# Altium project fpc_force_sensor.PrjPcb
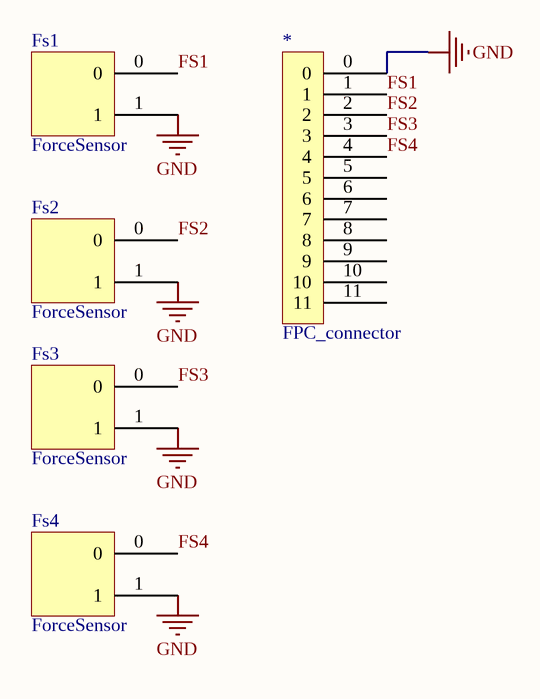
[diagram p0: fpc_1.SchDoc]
1 sheet, 5 parts. Net scope: global (net labels, ports and power ports of the same name join across sheets).
Board files: fpc1.PcbDoc, connectorPCB.PcbDoc

## Sheet fpc_1.SchDoc
size A; SheetNumber: 1; SheetTotal: 2

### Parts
*  FPC_connector  [FPC_connector]
Fs1  ForceSensor  [sensor_connector]
Fs2  ForceSensor  [sensor_connector]
Fs3  ForceSensor  [sensor_connector]
Fs4  ForceSensor  [sensor_connector]

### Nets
GND: *.0 Fs1.1 Fs2.1 Fs3.1 Fs4.1
FS1: *.1 Fs1.0
FS2: *.2 Fs2.0
FS3: *.3 Fs3.0
FS4: *.4 Fs4.0

Not connected (* = marked no-connect by the designer): * 5 6 7 8 9 10 11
